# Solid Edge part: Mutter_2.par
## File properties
Dokumentum tartalom típus: 0
Last saved by: ahadarics
Revision: 77
Sűrűség: 0,000 kg/m^3
Pontosság: 0,990
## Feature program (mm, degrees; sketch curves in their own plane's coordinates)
base feature "unnamed BaseFeature 1"
thread "unnamed Thread 1"
chamfer "unnamed Chamfer 1"
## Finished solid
Body 1: solid body, 26 faces, 66 edges, 41 vertices.
  Faces by surface: plane 14, cone 7, cylinder 5
  Edges by curve: line 36, circle 25, spline 5
Bounding box of the edges (mm): 64.722 x 64.722 x 10.000, from (-32.3612, -32.3612, 0) to (32.3612, 32.3612, 10).
Cylindrical faces by radius (mm): R21.688 x1, R32.5 x4
Conical faces (half-angle, radius in mm at the cone's reference point): 45 deg R21.688 x1, 45 deg R22.688 x1, 45 deg R32.25 x4, 60 deg R31 x1
Planar faces by outward normal: +x 3, +y 3, +z 1, -x 3, -y 3, -z 1
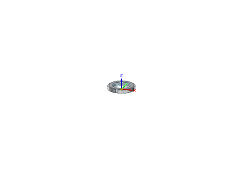
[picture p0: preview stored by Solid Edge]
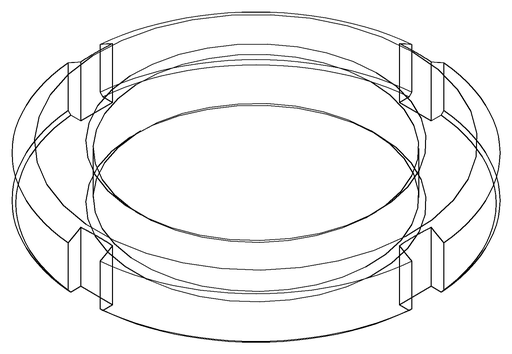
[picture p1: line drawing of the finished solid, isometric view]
